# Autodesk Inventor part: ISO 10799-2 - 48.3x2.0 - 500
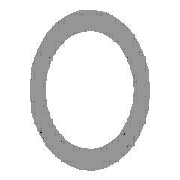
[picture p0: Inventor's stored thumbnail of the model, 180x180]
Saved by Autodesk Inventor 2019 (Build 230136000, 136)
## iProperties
Created: 2018-07
Part Number: ISO 10799-2 - 48.3x2.0 - 500
Material: Acier, doux
Description: Aciers de construction - Coupes creuses profilées formées à froid, soudées
Document SubType Name: Modeling
Standard: ISO
Designer: Fabian Perrée
Standard Revision: First edition 2011-09-15
Standards Organization: ISO
Language: fr-FR
Size Designation: 48.3x2.0
Categories: <MemberInstance><Categories><Category DisplayName="Profilés" InternalName="089c4875-fa83-4c05-b084-43b9cc11f5ed" Mnemonic="GRDR"><CategoryParameter DisplayName=
Stock Number: 48.3x2.0
Density: 7.85 g/cm^3
Appearance: Semi-poli
IsCustomPart: 1
_CCFamilyMember: 14
_CCFamilyDisplayName: ISO 10799-2 (Profils creux circulaires - Formés à froid) - Aciers de construction - Coupes creuses profilées formées à froid, soudées
_FrameMemberDoc: Frame Member File
_Version: 15.0.0
_GetPNFromCC: 1
Author: Fabian Perrée
G_L: 500,000 mm
G_W: 48,300 mm
G_H: 48,300 mm
+AB852084-64D8-4805-9BA0-F1D26D228743+DETAILDECOUPE1: Grugeage
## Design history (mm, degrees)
node "Plan de départ"
node "Plan de fin"
sketch "Esquisse"
  geometry: C1 r 22.15 at (0, 0); C2 r 24.15 at (0, 0); 2 further points
  constraints: 3 coincident, 2 centre point
  dimensions: "d0" = 48.3 diameter of C2 (= G_H); "d1" = 2 radial gap between concentric circles of C2 C1 (= G_T)
extrude "Corps" new body sketch "Esquisse" stored distance "d2" = 500 (= G_L); taper "d3" = 0 deg
node "Driven Length"
  sketch "Sketch3"
    geometry: L1 (0, 0)-(10, 0) reference
    constraints: 2 end point, 1 horizontal
  workplane "Work Plane3"
  sketch "Sketch4"
    geometry: L1 (-2, 0)-(12, 0) reference; L2 (-2, 500)-(12, 500) reference
    dimensions: "d7" = 500 distance between parallel lines of L1 L2 (derived)
body "Solid1"
feature "Sculpter1"
feature "Combiner1"
body "Srf5"
body "Srf6"
node "Solide3"
feature "Surface1"
body "Srf4"
feature "Carreau délimité3" dims "d12" = 5, "d13" = 0
feature "Carreau délimité4" dims "d14" = 5, "d15" = 0
other parameters: "G_H" = 48.3 [user parameter; used in 1 equation term], "G_T" = 2 [user parameter; used in 1 equation term], "G_L" = 500 (= d7) [user parameter; used in 1 equation term], "G_OFFSET_START" = 0 [user parameter; used in 1 equation term], "G_OFFSET_END" = 0 [user parameter; used in 1 equation term], "d4" = 0 (computed from G_OFFSET_START), "d5" = 500 (= G_OFFSET_END + B_L), "B_L" = 500 [user parameter; used in 1 equation term], "d6" = 90 deg, "MAS" = 0.228 [user parameter]
